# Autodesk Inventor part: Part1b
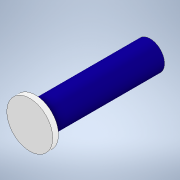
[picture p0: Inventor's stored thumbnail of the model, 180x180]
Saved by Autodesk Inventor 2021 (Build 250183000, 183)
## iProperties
Created: 2025-05
Part Number: Part1b
Material: Generic
Document SubType Name: Modeling
Designer: Aaditya
Density: 1 g/cm^3
Appearance: Default
Author: Aaditya
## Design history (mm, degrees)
sketch "Sketch3"
  geometry: C1 r 125 at (0, 0); C2 r 200 at (0, 0); 1 further point
  constraints: 2 centre point, 2 coincident
  dimensions: "d6" = 250 diameter of C1; "d7" = 400 diameter of C2
extrude "Extrusion3" new body sketch "Sketch3" distance "d8" = 50; taper "d9" = 0 deg
sketch "Sketch4"
  geometry: C1 r 125 at (0, 0); C2 r 100 at (0, 0); 1 further point
  constraints: 2 centre point, 2 coincident
  dimensions: "d10" = 250 diameter of C1; "d11" = 200 diameter of C2
extrude "Extrusion4" join sketch "Sketch4" distance "d12" = 1000; taper "d13" = 0 deg
body "Solid2"
